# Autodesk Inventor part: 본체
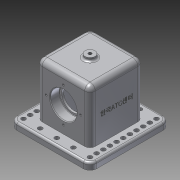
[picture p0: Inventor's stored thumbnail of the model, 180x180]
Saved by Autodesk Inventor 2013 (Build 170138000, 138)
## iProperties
Created: 2018-11
Part Number: 본체
Material: 알루미늄 6061
Document SubType Name: Modeling
Designer: Administrator
Mass: 1019.13 g
Surface Area: 780.986 cm^2
Volume: 376.063 cm^3
Density: 2.71 g/cm^3
Author: Administrator
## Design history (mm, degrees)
sketch "스케치1"
  geometry: L1 (-40, -45)-(40, -45); L2 (40, -45)-(40, 45); L3 (40, 45)-(-40, 45); L4 (-40, 45)-(-40, -45); L5 (-40, -45)-(40, 45); L6 (40, -45)-(-40, 45); 1 further point
  constraints: 12 end point, 2 midpoint, 2 parallel, 1 horizontal, 1 perpendicular
  dimensions: "d0" = 80 distance of L2.end L3.end; "d2" = 90 distance of L1.end L2.end
extrude "돌출1" new body sketch "스케치1" stored distance "d3" = 80; taper "d4" = 0 deg
sketch "스케치2"
  geometry: L1 (80, -80)-(80, 0) reference; L2 (0, 0)-(80, 0) reference; L3 (0, 0)-(0, -80) reference; L4 (80, -80)-(0, -80) reference; L5 (-20, -100)-(100, -100); L6 (100, -100)-(100, 20); L7 (100, 20)-(-20, 20); L8 (-20, 20)-(-20, -100); L9 (-20, -100)-(100, 20); L10 (100, -100)-(-20, 20); 1 further point
  constraints: 12 end point, 2 midpoint, 2 parallel, 1 horizontal, 1 perpendicular
  dimensions: "d5" = 120 distance of L6.end L7.end; "d7" = 120 distance of L5.end L6.end
extrude "돌출2" join sketch "스케치2" distance "d8" = 10; taper "d9" = 0 deg
sketch "스케치3"
  geometry: L1 (60, -45)-(-60, -45) reference; 2 further points
  constraints: 1 vertical alignment
  dimensions: "d10" = 48 distance from line of L1 point (0, 3)
hole "구멍1" sketch "스케치3" at (0, 3) diameter "d11" = 33; stored, may be unused: countersink angle "d15" = 90 deg, drill point angle "d17" = 118 deg; dims "d12" = 6, "d13" = 40, "d14" = 14, "d16" = 8
sketch "스케치4"
  geometry: C1 r 20 at (0, 3) reference; 2 further points
  constraints: 1 vertical alignment
  dimensions: "d18" = 26 distance of C1.centre point (0, 29)
hole "구멍2" sketch "스케치4" at (0, 29) diameter "d19" = 3.242; stored, may be unused: countersink angle "d23" = 90 deg, drill point angle "d25" = 118 deg; dims "d20" = 8, "d21" = 40, "d22" = 14, "d24" = 10
sketch "스케치5"
  geometry: L1 (30, 37)-(90, 37); L2 (90, 37)-(90, 83); L3 (90, 83)-(30, 83); L4 (30, 83)-(30, 37); L5 (30, 37)-(90, 83); L6 (90, 37)-(30, 83); 1 further point
  constraints: 12 end point, 2 midpoint, 2 parallel, 1 horizontal, 1 perpendicular
  dimensions: "d29" = 60 distance of L2.end L3.end; "d31" = 46 distance of L3.end L1.start
extrude "돌출3" cut sketch "스케치5" distance "d32" = 80; taper "d33" = 0 deg
sketch "스케치6"
  geometry: C1 r 7.5 at (40, 40); 1 further point
  constraints: 1 centre point, 1 coincident
  dimensions: "d34" = 15 diameter of C1
extrude "돌출4" join sketch "스케치6" distance "d36" = 5; taper "d37" = 0 deg
hole "구멍3" diameter "d40" = 4.917; stored, may be unused: countersink angle "d44" = 90 deg, drill point angle "d46" = 118 deg; dims "d38" = 10, "d39" = 10, "d41" = 8, "d42" = 40, "d43" = 14, "d45" = 10
sketch "스케치7"
  geometry: L1 (-10, -10)-(90, -10); L2 (90, -10)-(90, 90); L3 (90, 90)-(-10, 90); L4 (-10, 90)-(-10, -10); L5 (-10, -10)-(90, 90); L6 (90, -10)-(-10, 90); 2 further points
  constraints: 12 end point, 2 midpoint, 2 parallel, 1 coincident, 1 horizontal, 1 perpendicular
  dimensions: "d47" = 100 distance of L2.end L3.end; "d49" = 100 distance of L3.end L1.start
hole "구멍4" sketch "스케치7" at (-10, 90) diameter "d50" = 6.6; stored, may be unused: countersink angle "d54" = 90 deg, drill point angle "d56" = 118 deg; dims "d51" = 8, "d52" = 40, "d53" = 14, "d55" = 10
chamfer "모따기1" distance "d69" = 1; stored, may be unused: second distance "d70" = 2, angle "d71" = 45 deg
fillet "모깎기1" dims "d72" = 0.6
fillet "모깎기2" dims "d73" = 10
fillet "모깎기3" dims "d74" = 8
fillet "모깎기4" dims "d75" = 8
fillet "모깎기5" dims "d76" = 3
fillet "모깎기6" dims "d77" = 3
sketch "스케치8"
  geometry: L1 (82, -10)-(-18, -10) reference; 2 further points
  constraints: 1 vertical alignment, 1 other
  dimensions: "d78" = 48 distance from line of L1 point (32, 38)
feature "엠보싱1" sketch "스케치8" dims "d0" = 80, "d2" = 90, "d79" = 0.5, "d80" = 0
node "솔리드1"
pattern_circular "원형 패턴1" dims angle "d27" = 360 deg
mirror "대칭2"
pattern_linear "직사각형 패턴1" dims "d59" = 25
pattern_linear "직사각형 패턴2" dims "d65" = 10
